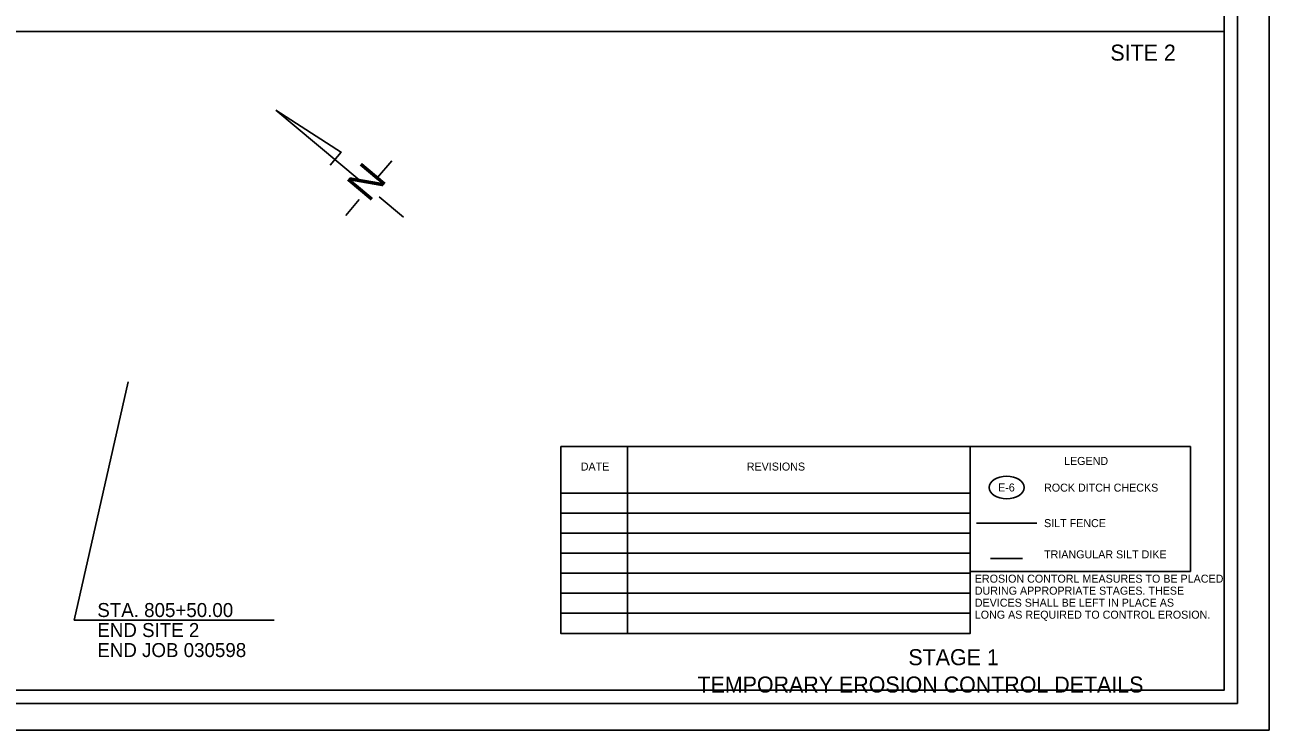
# Model space of a CAD drawing. Extents: x 814841 to 962585, y -174183 to 1802800.
# Drawn here: x 817705 to 818638, y 1801733 to 1802262 of the extents above; entities that cross this region are included whole.
import ezdxf

# ---------------------------------------------------------------- set-up
doc = ezdxf.new("R2010")
doc.units = 0
for name, color, linetype in [('_Silt Dike Legend', 7, 'Continuous'), ('Default', 7, 'Continuous'), ('Legend', 7, 'Continuous'), ('R_Border', 7, 'Continuous'), ('R_Border Notes', 7, 'Continuous'), ('R_Border Title', 7, 'Continuous'), ('R_Detour Annot', 7, 'Continuous'), ('R_Draft', 7, 'Continuous'), ('R_No Plot', 7, 'Continuous')]:
    doc.layers.add(name, color=color, linetype=linetype)

# ---------------------------------------------------------------- blocks, each defined once
blk = doc.blocks.new('E-6')
at = {"layer": 'Default'}
blk.add_ellipse((0, 0), major_axis=(13.15, 0), ratio=0.638788, dxfattribs=at)
blk.add_text('E-6', height=6, dxfattribs=at).set_placement((-6.43, -3))

msp = doc.modelspace()

# ---------------------------------------------------------------- linework, layer by layer
at = {"layer": '_Silt Dike Legend'}
msp.add_line((818428.94, 1801862.13), (818452.94, 1801862.13), dxfattribs=at)
at = {"layer": 'Legend'}
msp.add_line((818418.51, 1801888.52), (818463.54, 1801888.52), dxfattribs=at)
msp.add_lwpolyline([(818413.75, 1801945.92), (818578.75, 1801945.92), (818578.75, 1801852.39), (818413.75, 1801852.39)], close=True, dxfattribs=at)
at = {"layer": 'R_Border'}
for q in [(818614, 1802780.6), (817033.1, 1801753.3)]:
    msp.add_line((818614, 1801753.3), q, dxfattribs=at)
at = {"layer": 'R_Border Notes'}
for p, q in [((818156.73, 1801945.92), (818413.75, 1801945.92)), ((818156.73, 1801945.92), (818156.73, 1801805.92)), ((818106.73, 1801910.92), (818413.75, 1801910.92)), ((818106.73, 1801895.92), (818413.75, 1801895.92)), ((818106.73, 1801880.92), (818413.75, 1801880.92)), ((818106.73, 1801865.92), (818413.75, 1801865.92)), ((818106.73, 1801850.92), (818413.75, 1801850.92)), ((818106.73, 1801835.92), (818413.75, 1801835.92)), ((818106.73, 1801820.92), (818413.75, 1801820.92)), ((818106.73, 1801805.92), (818413.75, 1801805.92))]:
    msp.add_line(p, q, dxfattribs=at)
msp.add_lwpolyline([(818106.73, 1801945.92), (818413.75, 1801945.92), (818413.75, 1801805.92), (818106.73, 1801805.92)], close=True, dxfattribs=at)
at = {"layer": 'R_Draft'}
for p, q in [((817893.19, 1802198.16), (817942.44, 1802166.33)), ((817955.5, 1802145.86), (817893.19, 1802198.16)), ((817933.8, 1802156.71), (817942.11, 1802166.61)), ((817969.45, 1802147.56), (817980.05, 1802160.18)), ((817988.93, 1802117.8), (817970.6, 1802133.18)), ((817945.64, 1802119.2), (817955.56, 1802131.02)), ((817741.9, 1801815.89), (817782.46, 1801994.39)), ((817891.9, 1801815.89), (817741.9, 1801815.89))]:
    msp.add_line(p, q, dxfattribs=at)
at = {"layer": 'R_No Plot'}
for points in [[(816971.06, 1802800.08), (818637.76, 1802800.08), (818637.76, 1801733.39), (816971.06, 1801733.39)], [(817043.1, 1802770.6), (818290.8, 1802770.6), (818290.8, 1802721.2), (818378.5, 1802721.2), (818499, 1802721.2), (818499, 1802609.54), (818604, 1802609.54), (818604, 1801763.3), (817043.1, 1801763.3)], [(817043.1, 1802256.95), (818604, 1802256.95), (818604, 1801763.3), (817043.1, 1801763.3)], [(817043.1, 1802256.95), (818604, 1802256.95), (818604, 1801763.3), (817043.1, 1801763.3)], [(817043.1, 1802256.95), (818604, 1802256.95), (818604, 1801763.3), (817043.1, 1801763.3)], [(817043.1, 1802256.95), (818604, 1802256.95), (818604, 1801763.3), (817043.1, 1801763.3)], [(817043.1, 1802256.95), (818604, 1802256.95), (818604, 1801763.3), (817043.1, 1801763.3)], [(817043.1, 1802256.95), (818604, 1802256.95), (818604, 1801763.3), (817043.1, 1801763.3)], [(817043.1, 1802256.95), (818604, 1802256.95), (818604, 1801763.3), (817043.1, 1801763.3)]]:
    msp.add_lwpolyline(points, close=True, dxfattribs=at)

# ---------------------------------------------------------------- block references
at = {"layer": 'Legend', "rotation": -1.8065126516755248e-10}
msp.add_blockref('E-6', (818441.02, 1801915.24), dxfattribs=at)

# ---------------------------------------------------------------- texts
at = {"layer": 'Legend'}
for s, p in [('LEGEND', (818484.06, 1801932.13)), ('DATE', (818121.73, 1801927.92)), ('  REVISIONS', (818241.73, 1801927.92)), ('ROCK DITCH CHECKS', (818469.06, 1801912.13)), ('SILT FENCE', (818469.06, 1801885.52)), ('TRIANGULAR SILT DIKE', (818469.06, 1801862.13)), ('EROSION CONTORL MEASURES TO BE PLACED', (818417.12, 1801843.9)), ('DURING APPROPRIATE STAGES. THESE ', (818417.12, 1801834.9)), ('DEVICES SHALL BE LEFT IN PLACE AS ', (818417.12, 1801825.9)), ('LONG AS REQUIRED TO CONTROL EROSION.', (818417.12, 1801816.9))]:
    msp.add_text(s, height=6, dxfattribs=at).set_placement(p)
at = {"layer": 'R_Border'}
msp.add_text('SITE 2', height=12, dxfattribs=at).set_placement((818518.76, 1802235.17))
at = {"layer": 'R_Border Title'}
for s, p in [('STAGE 1', (818367.33, 1801782.05)), ('TEMPORARY EROSION CONTROL DETAILS', (818209.2, 1801761.55))]:
    msp.add_text(s, height=12, dxfattribs=at).set_placement(p)
at = {"layer": 'R_Detour Annot'}
for s, p in [('STA. 805+50.00', (817759.28, 1801818.14)), ('END SITE 2', (817759.28, 1801803.14)), ('END JOB 030598', (817759.28, 1801788.14))]:
    msp.add_text(s, height=10.5, dxfattribs=at).set_placement(p)
at = {"layer": 'R_Draft'}
msp.add_text('N', height=23.27, rotation=49.991, dxfattribs=at).set_placement((817962.66, 1802128.33))

doc.saveas('drawing.dxf')
